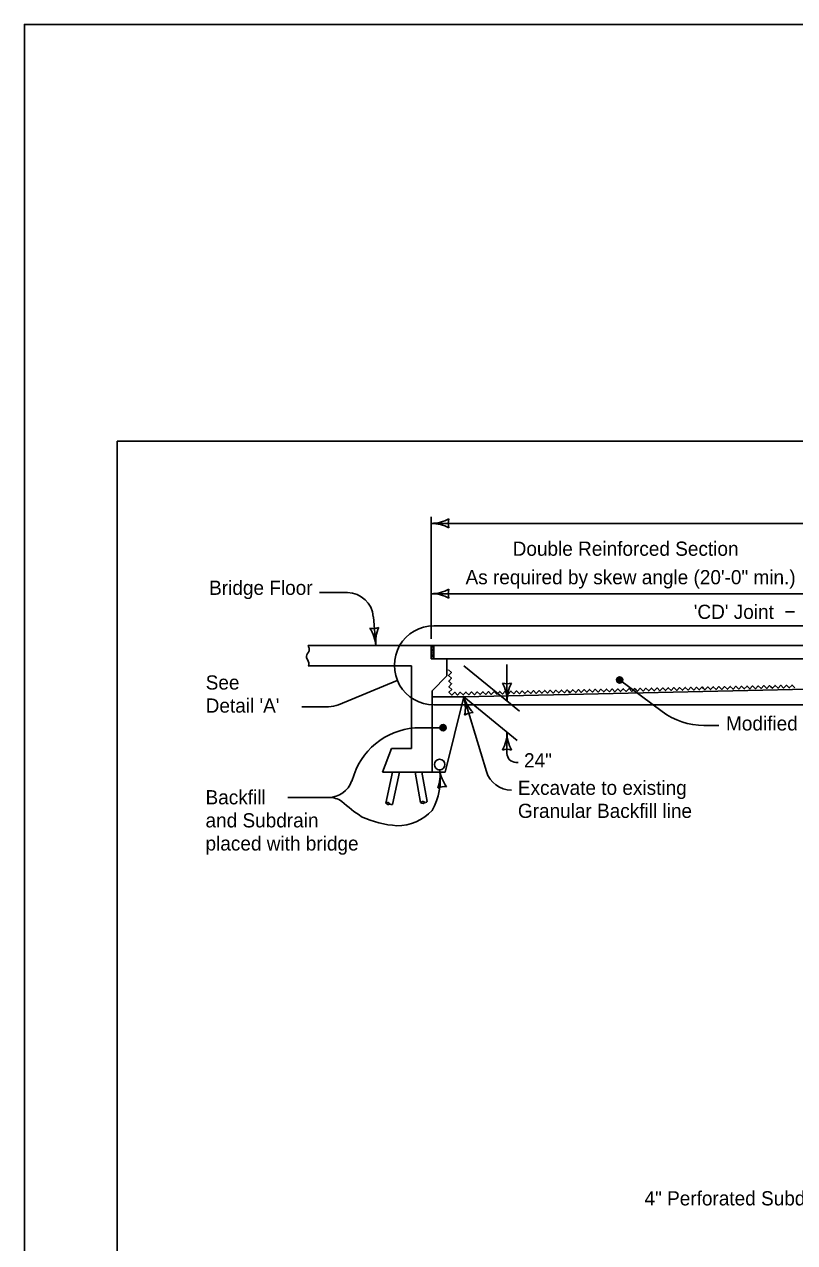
# Model space of a CAD drawing. Extents: x -2135039 to -2124495, y -2139046 to -2132546.
# Drawn here: x -2131439 to -2130571, y -2133919 to -2132546 of the extents above; entities that cross this region are included whole.
import ezdxf

# ---------------------------------------------------------------- set-up
doc = ezdxf.new("R2010")
doc.units = 0
for name, color, linetype in [('BridgeSuperStructureExisting', 7, 'Continuous'), ('dsnAlignmentStation', 7, 'Continuous'), ('dsnCellElements', 7, 'Continuous'), ('dsnStdLabel', 7, 'Continuous'), ('dsnStdLineWork', 7, 'Continuous')]:
    doc.layers.add(name, color=color, linetype=linetype)

msp = doc.modelspace()

# ---------------------------------------------------------------- linework, layer by layer
at = {"layer": 'BridgeSuperStructureExisting'}
for p, q in [((-2131074.8, -2133186.6), (-2131106.5, -2133186.6)), ((-2131008.7, -2133246.2), (-2131119.3, -2133246.2)), ((-2131008.7, -2133246.2), (-2130980.5, -2133246.2)), ((-2130980.5, -2133246.2), (-2130980.5, -2133261.2)), ((-2130977.5, -2133246.2), (-2130980.5, -2133246.2)), ((-2130980.5, -2133247.5), (-2130979.6, -2133246.6)), ((-2130980.5, -2133249.6), (-2130977.5, -2133246.6)), ((-2130977.5, -2133246.6), (-2130980.5, -2133246.6)), ((-2130980.5, -2133251.7), (-2130977.5, -2133248.7)), ((-2130980.5, -2133253.8), (-2130977.5, -2133250.8)), ((-2130980.5, -2133255.9), (-2130977.5, -2133252.9)), ((-2130977.5, -2133246.2), (-2130977.5, -2133261.2)), ((-2130977.5, -2133246.2), (-2129822.6, -2133246.2)), ((-2130980.5, -2133258), (-2130977.5, -2133255)), ((-2130980.5, -2133260.1), (-2130977.5, -2133257.1)), ((-2130980.5, -2133261.2), (-2130962.7, -2133261.2)), ((-2130979.5, -2133261.2), (-2130977.5, -2133259.2)), ((-2129836.3, -2133261.1), (-2130977.5, -2133261.1)), ((-2130940.4, -2133261.1), (-2130963.7, -2133261.1)), ((-2130962.7, -2133261.1), (-2130962.7, -2133280.4)), ((-2131002.8, -2133269.1), (-2131119.3, -2133269.1)), ((-2131002.8, -2133269.1), (-2131002.8, -2133362.1)), ((-2130962.7, -2133280.4), (-2130979.5, -2133297.2)), ((-2129826.7, -2133278.9), (-2130943.9, -2133304.1)), ((-2130979.5, -2133297.2), (-2130979.5, -2133388.8)), ((-2130943.9, -2133304.1), (-2130979.5, -2133304.1)), ((-2130964.6, -2133388.8), (-2130943.9, -2133304.1)), ((-2131035.4, -2133388.8), (-2131025.2, -2133362.1)), ((-2131002.8, -2133362.1), (-2131025.2, -2133362.1)), ((-2130979.5, -2133388.8), (-2131035.4, -2133388.8)), ((-2131024, -2133388.8), (-2131031.5, -2133423.6)), ((-2131016.4, -2133388.8), (-2131024.2, -2133425.2)), ((-2130998.7, -2133388.8), (-2130992.4, -2133423.1)), ((-2130991.2, -2133388.8), (-2130985.1, -2133421.8)), ((-2130979.5, -2133388.8), (-2130964.6, -2133388.8))]:
    msp.add_line(p, q, dxfattribs=at)
for points in [[(-2130958.7, -2133300.6), (-2130960.5, -2133298.9), (-2130957.4, -2133295.7), (-2130960.6, -2133292.6), (-2130957.5, -2133289.3), (-2130960.8, -2133286.2), (-2130957.7, -2133283), (-2130960.9, -2133279.9), (-2130957.8, -2133276.7), (-2130961.1, -2133273.6), (-2130960.9, -2133273.4)], [(-2130825.7, -2133297.7), (-2130824.1, -2133299.3), (-2130821, -2133296.1), (-2130817.7, -2133299.2), (-2130814.6, -2133295.9), (-2130811.4, -2133299), (-2130808.3, -2133295.8), (-2130805.1, -2133298.9), (-2130802, -2133295.6), (-2130798.7, -2133298.7), (-2130795.6, -2133295.5), (-2130792.4, -2133298.6), (-2130789.3, -2133295.4), (-2130786.1, -2133298.5), (-2130783, -2133295.2), (-2130779.7, -2133298.3), (-2130776.6, -2133295.1), (-2130773.4, -2133298.2), (-2130770.3, -2133295), (-2130767.1, -2133298.1), (-2130764, -2133294.8), (-2130760.7, -2133297.9), (-2130757.6, -2133294.7), (-2130754.4, -2133297.8), (-2130751.3, -2133294.6), (-2130749.7, -2133296.1)], [(-2130768, -2133281.8), (-2130769.2, -2133282.3), (-2130771, -2133282.9), (-2130771.3, -2133284.7), (-2130771.1, -2133286.3), (-2130769.9, -2133287.8), (-2130768.2, -2133287.7), (-2130766.4, -2133287.4), (-2130765.5, -2133286), (-2130765.3, -2133284.4), (-2130766.4, -2133282.4), (-2130767.7, -2133282.3), (-2130769.5, -2133282.7), (-2130771, -2133283.9), (-2130771, -2133285.6), (-2130769.8, -2133287), (-2130768.2, -2133287.2), (-2130766.4, -2133286.8), (-2130766.1, -2133285.8), (-2130765.7, -2133284.6), (-2130766.6, -2133283.1), (-2130767.9, -2133283.1), (-2130769.4, -2133283.3), (-2130770.5, -2133284.2), (-2130770, -2133285.7), (-2130768.8, -2133286.6), (-2130767.3, -2133286.6), (-2130766.9, -2133285.8), (-2130766.4, -2133284.9), (-2130767.2, -2133283.7), (-2130768.3, -2133283.4), (-2130769.3, -2133284), (-2130769.4, -2133285.1), (-2130768.8, -2133285.9), (-2130767.8, -2133286.1), (-2130767.3, -2133285.7), (-2130767, -2133285.1), (-2130767.6, -2133284.2), (-2130768.3, -2133284), (-2130769, -2133284.5), (-2130768.9, -2133285.1), (-2130768.3, -2133285.5), (-2130767.6, -2133285.4), (-2130767.6, -2133284.9), (-2130768.3, -2133284.6)], [(-2130749.7, -2133296.1), (-2130748.1, -2133297.7), (-2130745, -2133294.4), (-2130741.7, -2133297.5), (-2130738.6, -2133294.3), (-2130735.4, -2133297.4), (-2130732.3, -2133294.2), (-2130729.1, -2133297.3), (-2130726, -2133294), (-2130722.7, -2133297.1), (-2130719.6, -2133293.9), (-2130716.4, -2133297), (-2130713.3, -2133293.8), (-2130710.1, -2133296.8), (-2130707, -2133293.6), (-2130703.7, -2133296.7), (-2130700.6, -2133293.5), (-2130697.4, -2133296.6), (-2130694.3, -2133293.3), (-2130691, -2133296.4), (-2130687.9, -2133293.2), (-2130684.7, -2133296.3), (-2130681.6, -2133293.1), (-2130678.4, -2133296.2), (-2130675.3, -2133292.9), (-2130673.7, -2133294.5)], [(-2130673.7, -2133294.5), (-2130672, -2133296), (-2130668.9, -2133292.8), (-2130665.7, -2133295.9), (-2130662.6, -2133292.7), (-2130659.4, -2133295.8), (-2130656.3, -2133292.5), (-2130653, -2133295.6), (-2130649.9, -2133292.4), (-2130646.7, -2133295.5), (-2130643.6, -2133292.3), (-2130640.4, -2133295.4), (-2130637.3, -2133292.1), (-2130634, -2133295.2), (-2130630.9, -2133292), (-2130627.7, -2133295.1), (-2130624.6, -2133291.9), (-2130621.4, -2133295), (-2130618.3, -2133291.7), (-2130615, -2133294.8), (-2130611.9, -2133291.6), (-2130608.7, -2133294.7), (-2130605.6, -2133291.4), (-2130602.4, -2133294.5), (-2130599.3, -2133291.3), (-2130597.7, -2133292.9)], [(-2130597.7, -2133292.9), (-2130596, -2133294.4), (-2130592.9, -2133291.2), (-2130589.7, -2133294.3), (-2130586.6, -2133291), (-2130583.4, -2133294.1), (-2130580.3, -2133290.9), (-2130577, -2133294), (-2130573.9, -2133290.8), (-2130570.7, -2133293.9)], [(-2130960.3, -2133299), (-2130960.3, -2133299), (-2130957.1, -2133302.1), (-2130954, -2133298.9), (-2130950.8, -2133302), (-2130947.7, -2133298.8), (-2130944.4, -2133301.9), (-2130941.3, -2133298.6), (-2130938.1, -2133301.7), (-2130935, -2133298.5), (-2130931.8, -2133301.6), (-2130928.7, -2133298.4), (-2130925.4, -2133301.5), (-2130922.3, -2133298.2), (-2130919.1, -2133301.3), (-2130916, -2133298.1), (-2130912.8, -2133301.2), (-2130909.7, -2133297.9), (-2130906.4, -2133301), (-2130903.3, -2133297.8), (-2130901.7, -2133299.4)], [(-2130901.7, -2133299.4), (-2130900.1, -2133300.9), (-2130897, -2133297.7), (-2130893.8, -2133300.8), (-2130890.7, -2133297.5), (-2130887.4, -2133300.6), (-2130884.3, -2133297.4), (-2130881.1, -2133300.5), (-2130878, -2133297.3), (-2130874.8, -2133300.4), (-2130871.7, -2133297.1), (-2130868.4, -2133300.2), (-2130865.3, -2133297), (-2130862.1, -2133300.1), (-2130859, -2133296.9), (-2130855.7, -2133300), (-2130852.6, -2133296.7), (-2130849.4, -2133299.8), (-2130846.3, -2133296.6), (-2130843.1, -2133299.7), (-2130840, -2133296.5), (-2130836.7, -2133299.6), (-2130833.6, -2133296.3), (-2130830.4, -2133299.4), (-2130827.3, -2133296.2), (-2130825.7, -2133297.7)], [(-2130967.3, -2133341.9), (-2130966.2, -2133341.4), (-2130964.4, -2133340.9), (-2130964, -2133339), (-2130964.3, -2133337.4), (-2130965.4, -2133335.9), (-2130967.1, -2133336), (-2130969, -2133336.3), (-2130969.8, -2133337.8), (-2130970, -2133339.3), (-2130968.9, -2133341.3), (-2130967.6, -2133341.5), (-2130965.8, -2133341), (-2130964.3, -2133339.8), (-2130964.3, -2133338.1), (-2130965.5, -2133336.7), (-2130967.1, -2133336.6), (-2130969, -2133336.9), (-2130969.2, -2133337.9), (-2130969.6, -2133339.2), (-2130968.7, -2133340.7), (-2130967.4, -2133340.6), (-2130965.9, -2133340.4), (-2130964.8, -2133339.5), (-2130965.4, -2133338), (-2130966.5, -2133337.1), (-2130968, -2133337.1), (-2130968.4, -2133337.9), (-2130968.9, -2133338.8), (-2130968.1, -2133340), (-2130967, -2133340.3), (-2130966, -2133339.8), (-2130965.9, -2133338.7), (-2130966.5, -2133337.9), (-2130967.5, -2133337.6), (-2130968, -2133338), (-2130968.3, -2133338.6), (-2130967.8, -2133339.5), (-2130967, -2133339.7), (-2130966.3, -2133339.3), (-2130966.5, -2133338.7), (-2130967, -2133338.3), (-2130967.7, -2133338.3), (-2130967.7, -2133338.8), (-2130967.1, -2133339.1)]]:
    msp.add_lwpolyline(points, dxfattribs=at)
for centre, radius in [((-2130768.2, -2133285), 3.46), ((-2130967.1, -2133338.8), 3.46), ((-2130971, -2133380.3), 5.94)]:
    msp.add_circle(centre, radius, dxfattribs=at)
for centre, radius, start, end in [((-2131075.3, -2133216.3), 29.7, 4.9696, 89.1065), ((-2130895.1, -2133272.8), 16.5, 252.2666, 287.7333), ((-2130937.8, -2133308.6), 42.7, 360, 28.0725), ((-2130895.1, -2133272.8), 16.5, 252.2666, 287.7333), ((-2130937.8, -2133308.6), 42.7, 360, 28.0725), ((-2130852.3, -2133308.6), 42.7, 151.9275, 180), ((-2130852.3, -2133308.6), 42.7, 151.9275, 180), ((-2130992.8, -2133418), 79.2, 90, 160.3012), ((-2130885.1, -2133367.8), 10, 180, 270), ((-2131096.2, -2133389.5), 27.7, 270, 340.3019), ((-2131096.2, -2133444.9), 27.7, 56.8248, 90)]:
    msp.add_arc(centre, radius, start, end, dxfattribs=at)
for points in [[(-2131119.3, -2133246.2), (-2131118.1, -2133252.2), (-2131121.1, -2133258.2), (-2131118.4, -2133265.8), (-2131118.8, -2133269.1)], [(-2131031.5, -2133423.6), (-2131028.4, -2133423.3), (-2131026.6, -2133425), (-2131024.2, -2133425.2)], [(-2131031.5, -2133423.6), (-2131029.4, -2133425.1), (-2131026.9, -2133424.9)], [(-2130992.4, -2133423.1), (-2130989.6, -2133422), (-2130986.8, -2133423.2), (-2130985.1, -2133421.8)], [(-2130992.4, -2133423.1), (-2130989.7, -2133424.1), (-2130987.6, -2133423.2)]]:
    msp.add_spline(points, degree=3, dxfattribs=at)
at = {"layer": 'dsnAlignmentStation'}
msp.add_lwpolyline([(-2131334.4, -2133016), (-2128199.4, -2133016), (-2128199.4, -2135026), (-2131334.4, -2135026)], close=True, dxfattribs=at)
at = {"layer": 'dsnCellElements'}
for centre, radius, start, end in [((-2130980.5, -2133066.1), 42.5, 270, 298.0725), ((-2130980.5, -2133151.1), 42.5, 61.9275, 90), ((-2130944.9, -2133108.6), 16.4, 162.2666, 197.7334), ((-2130980.5, -2133145.3), 42.5, 270, 298.0725), ((-2130944.9, -2133187.8), 16.4, 162.2666, 197.7334), ((-2130980.5, -2133230.3), 42.5, 61.9275, 90), ((-2131045.9, -2133210.7), 16.4, 257.2333, 292.7), ((-2131000.5, -2133242.5), 42.5, 156.8942, 184.9667), ((-2131085.2, -2133249.9), 42.5, 4.9667, 33.0392), ((-2130903.2, -2133291.7), 42.5, 196.9516, 225.0241), ((-2130984.5, -2133316.5), 42.5, 348.8791, 16.9516), ((-2130933.5, -2133338.2), 16.4, 89.2182, 124.6849), ((-2130937.6, -2133343.9), 42.5, 331.9275, 360), ((-2130852.6, -2133343.9), 42.5, 180, 208.0725), ((-2130895.1, -2133379.5), 16.4, 72.2666, 107.7334), ((-2131013, -2133392.6), 42.5, 340.519, 8.5915), ((-2130929, -2133379.9), 42.5, 188.5915, 216.6639), ((-2130965.7, -2133421.4), 16.4, 80.8581, 116.3248)]:
    msp.add_arc(centre, radius, start, end, dxfattribs=at)
at = {"layer": 'dsnStdLabel'}
for p, q in [((-2130980.5, -2133238.8), (-2130980.5, -2133101.2)), ((-2130980.5, -2133108.6), (-2129641, -2133108.6)), ((-2130980.5, -2133187.8), (-2130532, -2133187.8)), ((-2130581.3, -2133208.2), (-2130571, -2133208.2)), ((-2131045.7, -2133213.7), (-2131042.8, -2133246.2)), ((-2130977.5, -2133223.9), (-2130174.4, -2133223.9)), ((-2130977.5, -2133261.1), (-2130977.5, -2133246.2)), ((-2130977.5, -2133246.2), (-2130532, -2133246.2)), ((-2130962.7, -2133261.1), (-2130977.5, -2133261.1)), ((-2130940.4, -2133261.1), (-2130962.7, -2133261.1)), ((-2130532, -2133261.1), (-2130940.4, -2133261.1)), ((-2130895.1, -2133308.6), (-2130895.1, -2133267.4)), ((-2130943.9, -2133268.9), (-2130881.1, -2133320)), ((-2131018.7, -2133285.5), (-2131084.9, -2133312.9)), ((-2130720.3, -2133320.6), (-2130768.2, -2133285)), ((-2130943.9, -2133304.1), (-2130883.6, -2133353.2)), ((-2130918.3, -2133388.1), (-2130943.9, -2133304.1)), ((-2131096.2, -2133315.1), (-2131126.2, -2133315.1)), ((-2130977.5, -2133313), (-2130174.4, -2133313)), ((-2130656.2, -2133336.2), (-2130673.1, -2133336.2)), ((-2130992.8, -2133338.8), (-2130967.1, -2133338.8)), ((-2130895.1, -2133367.8), (-2130895.1, -2133343.9)), ((-2131070.1, -2133398.8), (-2131067.4, -2133391.3)), ((-2130885.1, -2133377.8), (-2130882.6, -2133377.8)), ((-2131141.9, -2133417.2), (-2131096.2, -2133417.2))]:
    msp.add_line(p, q, dxfattribs=at)
for centre, radius, start, end in [((-2130977.5, -2133268.5), 44.5, 89.9996, 270), ((-2131096.2, -2133285.4), 29.7, 270, 292.4496), ((-2130673.1, -2133257), 79.2, 233.4243, 270), ((-2131041.5, -2133396.8), 71.3, 330.5092, 8.5915), ((-2130889.9, -2133379.4), 29.7, 196.9535, 270), ((-2130969.8, -2133301.8), 163.6, 227.1442, 236.9942), ((-2131019.4, -2133394.3), 55, 270.3325, 316.7198), ((-2131009.9, -2133331.1), 118.5, 245.5915, 265.546)]:
    msp.add_arc(centre, radius, start, end, dxfattribs=at)
at = {"layer": 'dsnStdLineWork'}
msp.add_lwpolyline([(-2131438.9, -2135130.5), (-2128094.9, -2135130.5), (-2128094.9, -2132546.5), (-2131438.9, -2132546.5)], close=True, dxfattribs=at)

# ---------------------------------------------------------------- texts
at = {"layer": 'dsnStdLabel'}
for s, p in [('Double Reinforced Section', (-2130888.7, -2133145.1)), ('As required by skew angle (20\'-0" min.)', (-2130941.8, -2133177.2)), ('Bridge Floor', (-2131230.7, -2133189.1)), ("'CD' Joint", (-2130684.6, -2133216.2)), ('See', (-2131234.6, -2133295.8)), ("Detail 'A'", (-2131234.6, -2133321.8)), ('Modified Subbase', (-2130648.3, -2133341.9)), ('24"', (-2130875.9, -2133383.5)), ('Excavate to existing', (-2130882.8, -2133414.4)), ('Backfill', (-2131234.8, -2133425.1)), ('Granular Backfill line', (-2130882.8, -2133440.4)), ('and Subdrain', (-2131234.8, -2133451.1)), ('placed with bridge', (-2131234.8, -2133477.1)), ('4" Perforated Subdrain', (-2130740.1, -2133876.9))]:
    msp.add_text(s, height=16, dxfattribs=at).set_placement(p)

doc.saveas('drawing.dxf')
